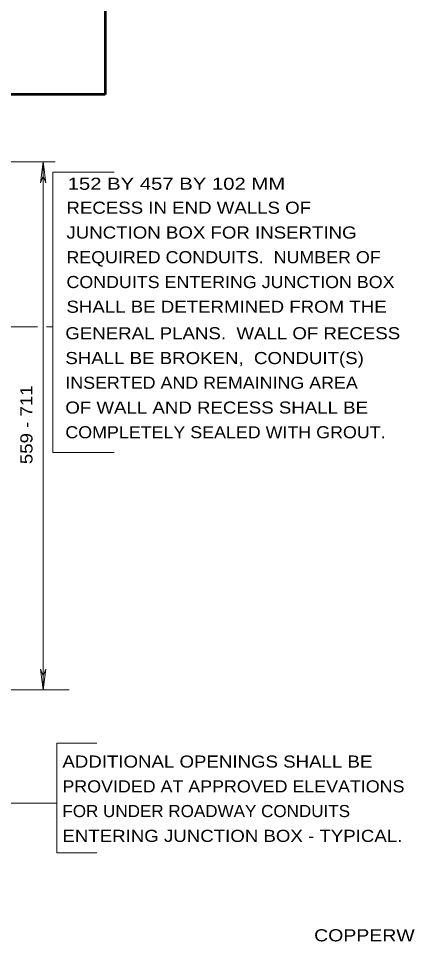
# Model space of a CAD drawing. Extents: x 312583 to 312854, y 144419 to 144597.
# Drawn here: x 312670 to 312694.4, y 144468.2 to 144526.1 of the extents above; entities that cross this region are included whole.
import ezdxf

# ---------------------------------------------------------------- set-up
doc = ezdxf.new("R2010")
doc.units = 0
doc.header["$LTSCALE"] = 0.3
doc.layers.add('1', color=7, linetype='Continuous', lineweight=40)
doc.layers.add('2', color=7, linetype='Continuous', lineweight=13)

msp = doc.modelspace()

# ---------------------------------------------------------------- linework, layer by layer
at = {"layer": '1', "lineweight": 53}
for p, q in [((312675.4374, 144585.0846), (312675.4374, 144521.3091)), ((312675.4374, 144521.3091), (312616.5, 144521.3091))]:
    msp.add_line(p, q, dxfattribs=at)
at = {"layer": '2'}
for p, q in [((312664.1406, 144517.0786), (312672.2979, 144517.0786)), ((312671.5466, 144517.0786), (312671.3856, 144515.7753)), ((312671.5466, 144517.0786), (312671.7076, 144515.7753)), ((312671.5466, 144483.9586), (312671.5466, 144517.0786)), ((312675.9856, 144516.4346), (312672.1523, 144516.4346)), ((312672.1523, 144498.8473), (312672.1523, 144516.4346)), ((312671.3856, 144515.7753), (312671.5466, 144516.1893)), ((312671.7076, 144515.7753), (312671.5466, 144516.1893)), ((312669.5379, 144506.7363), (312671.1939, 144506.7363)), ((312671.7536, 144506.7363), (312672.1523, 144506.7363)), ((312675.9856, 144498.8473), (312672.1523, 144498.8473)), ((312671.3856, 144485.262), (312671.5466, 144484.848)), ((312671.5466, 144483.9586), (312671.3856, 144485.262)), ((312671.7076, 144485.262), (312671.5466, 144484.848)), ((312671.5466, 144483.9586), (312671.7076, 144485.262)), ((312669.2926, 144483.9586), (312673.1796, 144483.9586)), ((312674.9046, 144480.616), (312672.4053, 144480.616)), ((312668.7559, 144476.867), (312672.4053, 144476.867))]:
    msp.add_line(p, q, dxfattribs=at)
msp.add_lwpolyline([(312674.9046, 144473.7466), (312672.4053, 144473.7466), (312672.4053, 144480.616)], dxfattribs=at)

# ---------------------------------------------------------------- texts
for s, width, p in [('152 BY 457 BY 102 MM', 1.25, (312673.0799, 144515.3296)), ('RECESS IN END WALLS OF', 1.15, (312673.0033, 144513.827)), ('JUNCTION BOX FOR INSERTING', 1.15, (312673.0033, 144512.2706)), ('REQUIRED CONDUITS.  NUMBER OF', 1.1, (312673.0033, 144510.722)), ('CONDUITS ENTERING JUNCTION BOX', 1.1, (312673.0033, 144509.1656)), ('SHALL BE DETERMINED FROM THE', 1.15, (312673.0033, 144507.617)), ('GENERAL PLANS.  WALL OF RECESS', 1.15, (312672.9343, 144505.9533)), ('SHALL BE BROKEN,  CONDUIT(S)', 1.15, (312672.9343, 144504.397)), ('INSERTED AND REMAINING AREA', 1.1, (312672.9343, 144502.8483)), ('OF WALL AND RECESS SHALL BE', 1.15, (312672.9343, 144501.292)), ('COMPLETELY SEALED WITH GROUT.', 1.1, (312672.9343, 144499.7433)), ('ADDITIONAL OPENINGS SHALL BE', 1.15, (312672.7503, 144479.0893)), ('PROVIDED AT APPROVED ELEVATIONS', 1.1, (312672.7503, 144477.533)), ('FOR UNDER ROADWAY CONDUITS', 1.05, (312672.7503, 144475.9843)), ('ENTERING JUNCTION BOX - TYPICAL.', 1.15, (312672.7503, 144474.428)), ('COPPERWELD-16 MM DIA. BY 3.7 M LG', 1.2, (312688.5229, 144468.1912))]:
    msp.add_text(s, height=0.76, dxfattribs=dict(at, width=width)).set_placement(p)
at = {"layer": '2', "width": 1.15}
msp.add_text('559 - 711', height=0.76, rotation=90, dxfattribs=at).set_placement((312670.8753, 144498.1225))

doc.saveas('drawing.dxf')
